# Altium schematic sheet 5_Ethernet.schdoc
size 309 x 223 mm; Symbol: Artery_A4; Device: Artery_A4; Company: Artery Technology; Drawed: SD; Version: 1.1; Page Size: A4; @Project Name: p_AT-START-F437; @Page Count: 5; @Update Date: 2023-04-14 17:11:57; @Create Date: 2022-12-01; @Schematic Name: AT-START-F437 V1.1; @Page No: 5; @Page Name: Ethernet
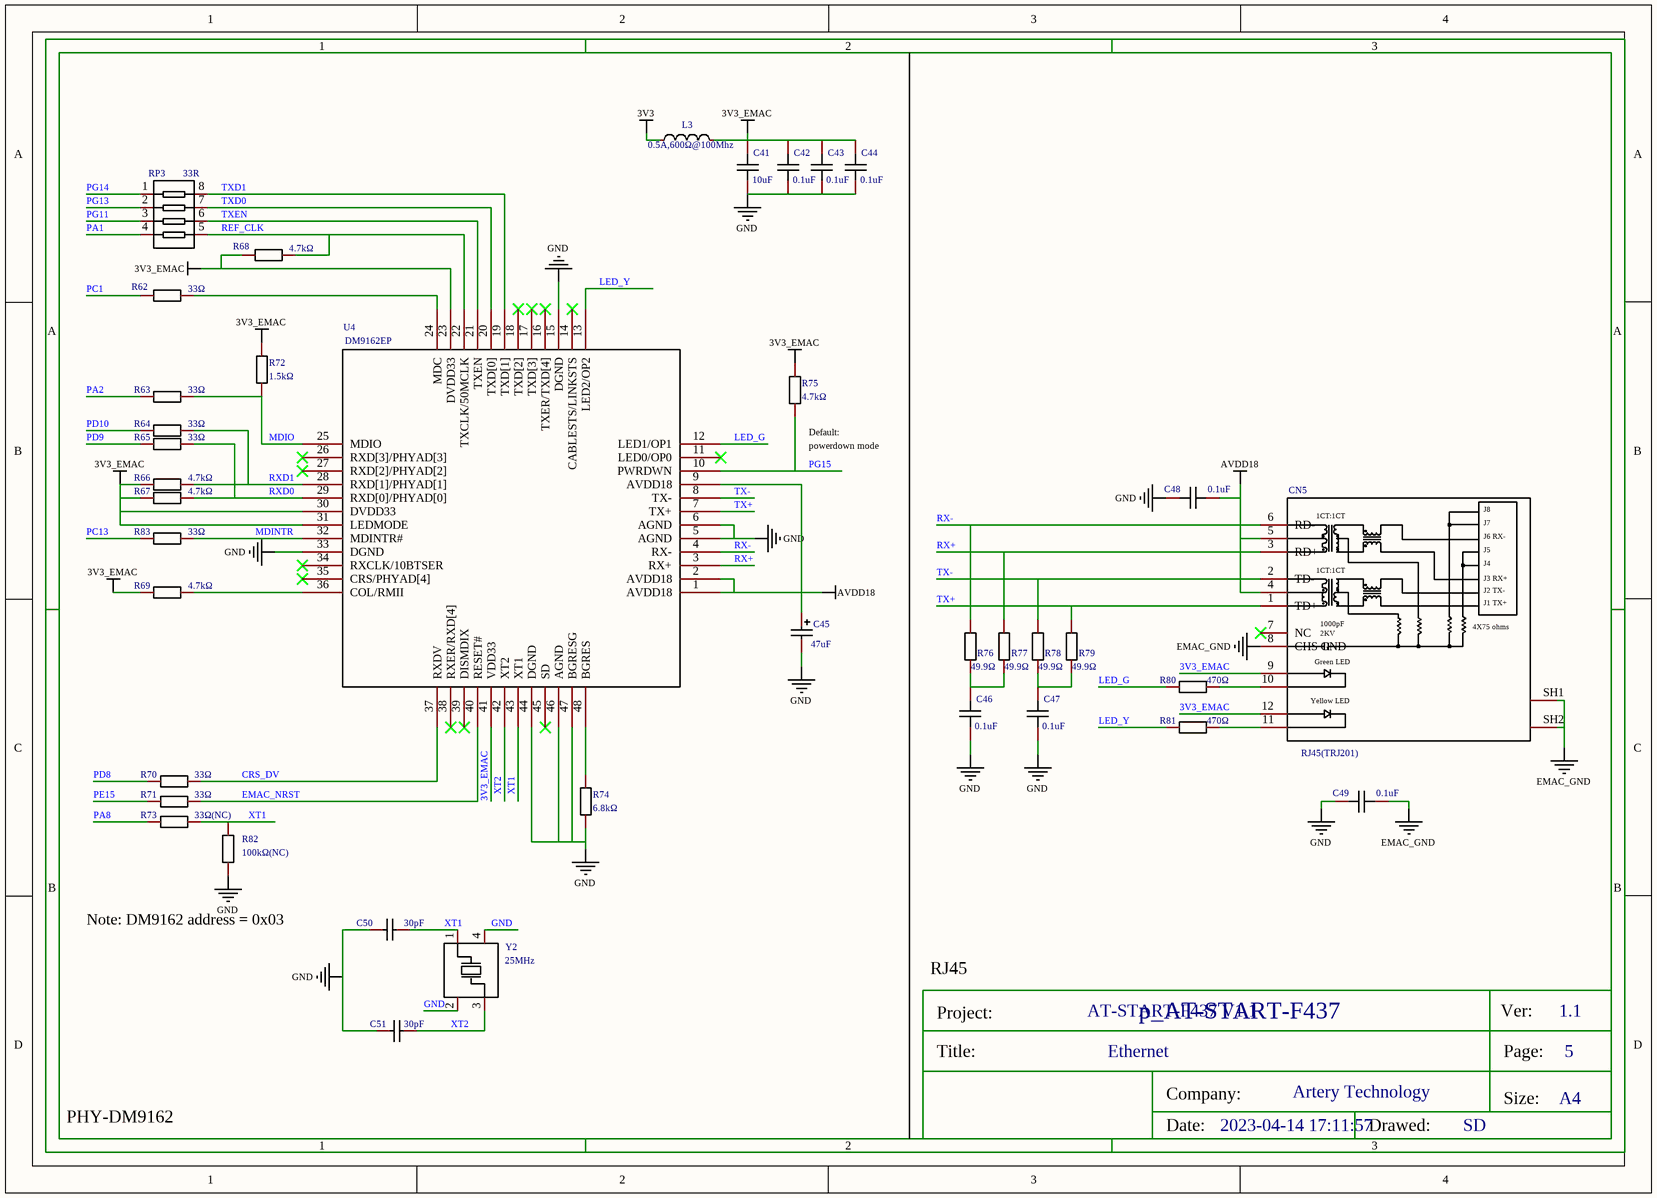
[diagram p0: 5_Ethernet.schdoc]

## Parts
C41  10uF  [0603_C-M]
C42  0.1uF  [0603_C-M]
C43  0.1uF  [0603_C-M]
C44  0.1uF  [0603_C-M]
C45  47uF  [CAP-SMD_L3.2-W1.6-R-RD]
C46  0.1uF  [0603_C-M]
C47  0.1uF  [0603_C-M]
C48  0.1uF  [0603_C-M]
C49  0.1uF  [0603_C-M]
C50  30pF  [C0603]
C51  30pF  [C0603]
CN5  RJ45(TRJ201)  [RJ45-TH_HR911105A]
L3  0.5A,600Ω@100Mhz  [0603_L]
R62  33Ω  [R0603]
R63  33Ω  [R0603]
R64  33Ω  [R0603]
R65  33Ω  [R0603]
R66  4.7kΩ  [R0603]
R67  4.7kΩ  [R0603]
R68  4.7kΩ  [R0603]
R69  4.7kΩ  [R0603]
R70  33Ω  [R0603]
R71  33Ω  [R0603]
R72  1.5kΩ  [R0603]
R73  33Ω(NC)  [R0603]
R74  6.8kΩ  [R0603]
R75  4.7kΩ  [R0603]
R76  49.9Ω  [R0603]
R77  49.9Ω  [R0603]
R78  49.9Ω  [R0603]
R79  49.9Ω  [R0603]
R80  470Ω  [R0603]
R81  470Ω  [R0603]
R82  100kΩ(NC)  [R0603]
R83  33Ω  [R0603]
RP3  33R  [0603*4,8P4R]
U4  DM9162EP  [LQFP48_7*7]
Y2  25MHz  [CRYSTAL-SMD_4P-L5.0-W3.2-BL]

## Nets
3V3: L3.1
3V3_EMAC: C41.1 C42.1 C43.1 C44.1 CN5.9 CN5.12 L3.2 R66.1 R67.1 R68.1 R69.1 R72.2 R75.2 U4.23(DVDD33) U4.30(DVDD33) U4.31(LEDMODE) U4.41(VDD33)
AVDD18: C45.1 C48.2 CN5.4 CN5.5 U4.1(AVDD18) U4.2(AVDD18) U4.9(AVDD18)
EMAC_GND: C49.2 CN5.8(CHS_GND) CN5.SH1 CN5.SH2
GND: C41.2 C42.2 C43.2 C44.2 C45.2 C46.2 C47.2 C48.1 C49.1 C50.2 C51.2 R74.1 R82.2 U4.5(AGND) U4.6(AGND) U4.15(DGND) U4.33(DGND) U4.44(DGND) U4.46(AGND) U4.47(BGRESG) Y2.2(GND) Y2.4(GND)
CRS_DV: R70.2 U4.37(RXDV)
EMAC_NRST: R71.2 U4.40(RESET#)
LED_G: R80.2 U4.12(LED1/OP1)
LED_Y: R81.2 U4.13(LED2/OP2)
MDINTR: R83.2 U4.32(MDINTR#)
MDIO: R63.2 R72.1 U4.25(MDIO)
PA1: RP3.4
PA2: R63.1
PA8: R73.1
PC1: R62.1
PC13: R83.1
PD8: R70.1
PD9: R65.1
PD10: R64.1
PE15: R71.1
PG11: RP3.3
PG13: RP3.2
PG14: RP3.1
PG15: R75.1 U4.10(PWRDWN)
REF_CLK: R68.2 RP3.5 U4.22(TXCLK/50MCLK)
RX+: CN5.3(RD+) R77.2 U4.3(RX+)
RX-: CN5.6(RD-) R76.2 U4.4(RX-)
RXD0: R65.2 R67.2 U4.29(RXD[0]/PHYAD[0])
RXD1: R64.2 R66.2 U4.28(RXD[1]/PHYAD[1])
TX+: CN5.1(TD+) R79.2 U4.7(TX+)
TX-: CN5.2(TD-) R78.2 U4.8(TX-)
TXD0: RP3.7 U4.20(TXD[0])
TXD1: RP3.8 U4.19(TXD[1])
TXEN: RP3.6 U4.21(TXEN)
XT1: C50.1 R73.2 R82.1 U4.43(XT1) Y2.1(OSC1)
XT2: C51.1 U4.42(XT2) Y2.3(OSC2)
NetC46_1: C46.1 R76.1 R77.1
NetC47_1: C47.1 R78.1 R79.1
NetCN5_10: CN5.10 R80.1
NetCN5_11: CN5.11 R81.1
NetR62_2: R62.2 U4.24(MDC)
NetR69_2: R69.2 U4.36(COL/RMII)
NetR74_2: R74.2 U4.48(BGRES)

Not connected (* = marked no-connect by the designer): CN5 7(NC)*; U4 11(LED0/OP0)* 14(CABLESTS/LINKSTS)* 16(TXER/TXD[4])* 17(TXD[3])* 18(TXD[2])* 26(RXD[3]/PHYAD[3])* 27(RXD[2]/PHYAD[2])* 34(RXCLK/10BTSER)* 35(CRS/PHYAD[4])* 38(RXER/RXD[4])* 39(DISMDIX)* 45(SD)*

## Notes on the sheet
- (near R75) Default:
- (near R75) powerdown mode
- (near R82) Note: DM9162 address = 0x03
- RJ45
- PHY-DM9162

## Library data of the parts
C41 = 10uF: Convert to PCB: yes
C42-C44 C46-C49 = 0.1uF: Convert to PCB: yes
C45 = CA45B-A-6.3V-47uF-K: Manufacturer: CEC; Paste Type: expand; Convert to PCB: yes
C50 C51 = 0603CG300J500NT: 容值:30pF;精度:±5%;额定电压:50V;材质(温度系数):C0G;; Manufacturer: FH(风华); Add into BOM: yes; Tolerance: ±5%; Voltage Rated: 50V; Temperature Coefficient: C0G
CN5 = HR911105A: Manufacturer: HANRUN; Paste Type: expand; Convert to PCB: yes
L3 = 0.5A,600Ω@100Mhz: Convert to PCB: yes
R62-R65 R70 R71 R73 R83 = 0603WAF330JT5E: 电阻类型:厚膜电阻;阻值:33Ω;精度:±1%;功率:100mW;温度系数:±100ppm/℃;最大工作电压:75V;工作温度范围:-55℃~+155℃;; Manufacturer: UNI-ROYAL(厚声); Add into BOM: yes; Tolerance: ±1%; Power(Watts): 100mW; Overload Voltage (Max): 75V
R66-R69 R75 = 0603WAF4701T5E: 电阻类型:厚膜电阻;阻值:4.7kΩ;精度:±1%;功率:100mW;温度系数:±100ppm/℃;最大工作电压:75V;工作温度范围:-55℃~+155℃;; Manufacturer: UNI-ROYAL(厚声); Add into BOM: yes; Tolerance: ±1%; Power(Watts): 100mW; Overload Voltage (Max): 75V
R72 = 0603WAF1501T5E: 电阻类型:厚膜电阻;阻值:1.5kΩ;精度:±1%;功率:100mW;温度系数:±100ppm/℃;最大工作电压:75V;工作温度范围:-55℃~+155℃;; Manufacturer: UNI-ROYAL(厚声); Add into BOM: yes; Tolerance: ±1%; Power(Watts): 100mW; Overload Voltage (Max): 75V
R74 = 0603WAF6801T5E: 电阻类型:厚膜电阻;阻值:6.8kΩ;精度:±1%;功率:100mW;温度系数:±100ppm/℃;最大工作电压:75V;工作温度范围:-55℃~+155℃;; Manufacturer: UNI-ROYAL(厚声); Add into BOM: yes; Tolerance: ±1%; Power(Watts): 100mW; Overload Voltage (Max): 75V
R76-R79 = 0603WAF499JT5E: 电阻类型:厚膜电阻;阻值:49.9Ω;精度:±1%;功率:100mW;温度系数:±100ppm/℃;最大工作电压:75V;工作温度范围:-55℃~+155℃;; Manufacturer: UNI-ROYAL(厚声); Add into BOM: yes; Tolerance: ±1%; Power(Watts): 100mW; Overload Voltage (Max): 75V
R80 R81 = 0603WAF4700T5E: 电阻类型:厚膜电阻;阻值:470Ω;精度:±1%;功率:100mW;温度系数:±100ppm/℃;最大工作电压:75V;工作温度范围:-55℃~+155℃;; Manufacturer: UNI-ROYAL(厚声); Add into BOM: yes; Tolerance: ±1%; Power(Watts): 100mW; Overload Voltage (Max): 75V
R82 = 0603WAF1003T5E: 电阻类型:厚膜电阻;阻值:100kΩ;精度:±1%;功率:100mW;温度系数:±100ppm/℃;最大工作电压:75V;工作温度范围:-55℃~+155℃;; Manufacturer: UNI-ROYAL(厚声); Add into BOM: yes; Tolerance: ±1%; Power(Watts): 100mW; Overload Voltage (Max): 75V
RP3 = 33R: Convert to PCB: yes
U4 = DM9162EP: Convert to PCB: yes
Y2 = X503225MSB4SI: 晶振类型:贴片无源晶振;频率:25MHz;频率公差:±10ppm;频率稳定度:±50ppm;负载电容:20pF;工作温度:-40℃~+85℃;; Manufacturer: YXC(扬兴晶振); Add into BOM: yes; Crystal Type: 贴片无源晶振; Frequency Tolerance: ±10ppm; Frequency Stability: ±50ppm; Load Capacitance: 20pF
